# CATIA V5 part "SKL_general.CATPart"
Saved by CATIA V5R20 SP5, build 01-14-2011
Part number: SKL_general
Publications: "Plan.1", "Point.1", "Droite.1", "Droite.2", "Esquisse.2", "Point.5", "Point.6", "Droite.3", "Point.7", "Point.8", "Droite.4", "Point.9", "Point.10", "Esquisse.3", "Point.11", "Point.12", "Droite.5", "Plan.11", "Point.2"
Bounding box of the stored display mesh (mm): x -32 to 20, y 0 to 160, z 0 to 0
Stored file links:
  F:\Catia_finish\SKL_general.CATPart
  F:\Catia_finish\ASS_compresseur.CATProduct
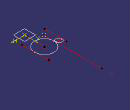
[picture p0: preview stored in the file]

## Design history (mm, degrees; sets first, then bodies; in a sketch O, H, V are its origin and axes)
External parameters (linked from other documents)
  External.longueur_bielle = 35 mm
  External.excentricite_vilebrequin = 6 mm
  External.rayon_secteur_dente = 20 mm
  External.longueur_tige = 119.3 mm
  External.rayon_pignon12 = 6 mm
Point1: (0, 0, 0)
Line1: type PtPt, FirstPoint Point11, SecondPoint Point10
Line2: type PtPt, FirstPoint Point4, SecondPoint Point5
Point2: (0, 6 {= External.excentricite_vilebrequin}, 0)
Set1 "set_geometrique"
  Plane1: type Offset, RefPlane xy-plane, Offset 0
  Point3: (0, 35 {= External.longueur_bielle}, 0), relative to Point2
  Line3: type PtPt, FirstPoint Point1, SecondPoint Point2
  Line4: type PtPt, FirstPoint Point2, SecondPoint Point3
  Sketch1 on xy-plane, origin (0, 0, 0), H (1, 0, 0), V (0, 1, 0)
    circle A1 centre (0, 41) radius 20
    point P1 (0, 41)
    reference projected point E1 (0, 41) from Point3
    radius A1 = 20 {= External.rayon_secteur_dente}
    coincidence: P1 E1
  Point4: (20 {= External.rayon_secteur_dente}, 70, 0)
  Point5: (20 {= External.rayon_secteur_dente}, 15, 0)
  Point6: (-20, 20, 0)
  Point7: (-20, 139.3 {= 20mm+External.longueur_tige}, 0)
  Line5: type PtPt, FirstPoint Point7, SecondPoint Point6
  Point8: (-20 {= -External.rayon_secteur_dente}, 160, 0)
  Point9: (-26 {= -External.rayon_secteur_dente -External.rayon_pignon12}, 45, 0)
  Sketch2 on xy-plane, origin (0, 0, 0), H (1, 0, 0), V (0, 1, 0)
    circle A1 centre (-26, 45) radius 6
    point P1 (-26, 45)
    reference projected point E1 (-26, 45) from Point9
    radius A1 = 6 {= External.rayon_pignon12}
    coincidence: P1 E1
  Point10: (-32 {= -External.rayon_secteur_dente -2*External.rayon_pignon12}, 10, 0)
  Point11: (-32 {= -External.rayon_secteur_dente -2*External.rayon_pignon12}, 55, 0)
Body1 (main body)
